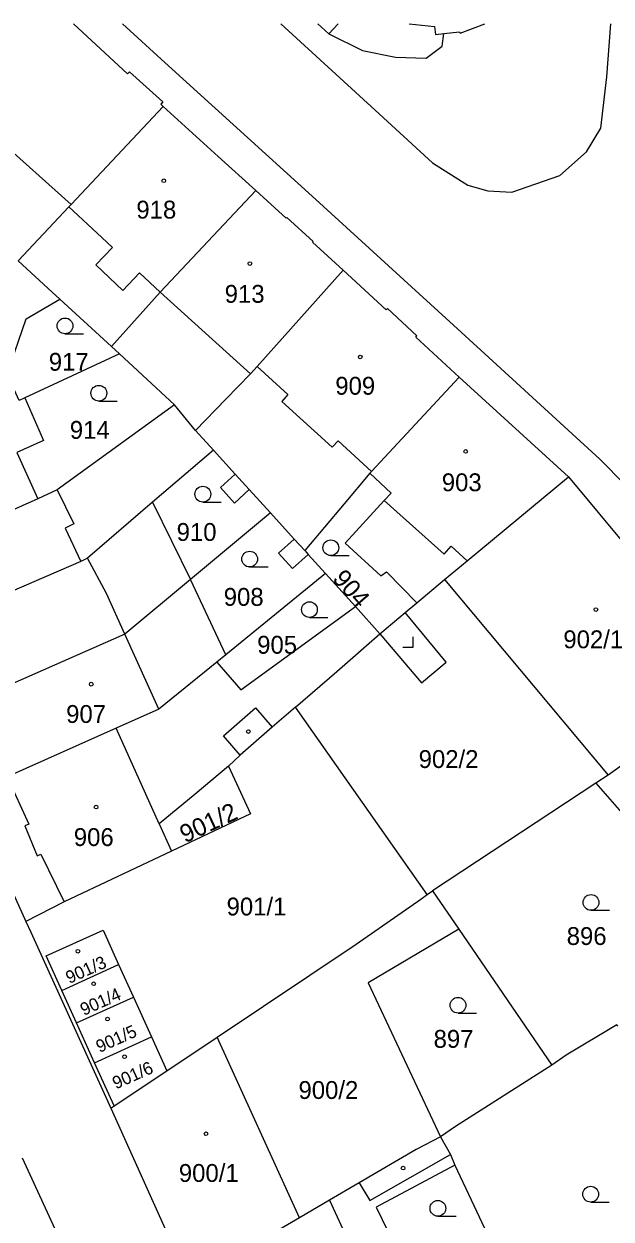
# Model space of a CAD drawing. Extents: x -496682 to -495907, y -1088575 to -1088018.
# Drawn here: x -496251.9 to -496196, y -1088133.3 to -1088019.5 of the extents above; entities that cross this region are included whole.
import ezdxf

# ---------------------------------------------------------------- set-up
doc = ezdxf.new("R2010")
doc.units = 0
for name, color, linetype in [('Hranice parcel', 7, 'Continuous'), ('Parcelní čísla', 7, 'Continuous'), ('Vnitřní kresba', 7, 'Continuous'), ('Značky budov', 7, 'Continuous'), ('Značky kultur', 7, 'Continuous')]:
    doc.layers.add(name, color=color, linetype=linetype)

msp = doc.modelspace()

# ---------------------------------------------------------------- linework, layer by layer
at = {"layer": 'Hranice parcel'}
for p, q in [((-496243.53, -1088050.21), (-496248.45, -1088045.69)), ((-496243.53, -1088050.21), (-496242.78, -1088050.9)), ((-496242.78, -1088050.9), (-496251.78, -1088055.1)), ((-496242.78, -1088050.9), (-496237.54, -1088055.74)), ((-496200.06, -1088062.62), (-496210.45, -1088053.11)), ((-496251.78, -1088055.1), (-496252.31, -1088055.35)), ((-496235.54, -1088058.2), (-496237.54, -1088055.74)), ((-496235.54, -1088058.2), (-496233.84, -1088060.08)), ((-496239.62, -1088065.03), (-496236.01, -1088072.37)), ((-496228.41, -1088066.04), (-496236.01, -1088072.37)), ((-496223.18, -1088071.81), (-496232.65, -1088079.55)), ((-496223.18, -1088071.81), (-496220.32, -1088074.97)), ((-496232.65, -1088079.55), (-496236.01, -1088072.37)), ((-496214.47, -1088074.6), (-496211.87, -1088072.4)), ((-496211.87, -1088072.4), (-496196.3, -1088091)), ((-496220.32, -1088074.97), (-496217.99, -1088077.55)), ((-496232.65, -1088079.55), (-496233.51, -1088080.25)), ((-496213.51, -1088102.38), (-496226.04, -1088084.55)), ((-496196.3, -1088091), (-496197.46, -1088091.77)), ((-496197.46, -1088091.77), (-496212.99, -1088102.02)), ((-496197.46, -1088091.77), (-496183.44, -1088107.88)), ((-496257.2, -1088092.78), (-496251.66, -1088104.94)), ((-496213.51, -1088102.38), (-496212.99, -1088102.02)), ((-496212.99, -1088102.02), (-496210.49, -1088105.69)), ((-496210.49, -1088105.69), (-496201.65, -1088118.63)), ((-496248.26, -1088111.5), (-496242.85, -1088109.04)), ((-496242.85, -1088109.04), (-496241.44, -1088112.14)), ((-496246.86, -1088114.6), (-496248.26, -1088111.5)), ((-496246.86, -1088114.6), (-496241.44, -1088112.14)), ((-496241.44, -1088112.14), (-496239.72, -1088115.94)), ((-496245.14, -1088118.39), (-496246.86, -1088114.6)), ((-496245.14, -1088118.39), (-496239.72, -1088115.94)), ((-496239.72, -1088115.94), (-496238.26, -1088119.15)), ((-496238.26, -1088119.15), (-496233.49, -1088115.96)), ((-496225.65, -1088133.15), (-496233.49, -1088115.96)), ((-496243.27, -1088122.51), (-496245.14, -1088118.39)), ((-496243.27, -1088122.51), (-496238.26, -1088119.15)), ((-496243.59, -1088122.72), (-496243.27, -1088122.51)), ((-496243.59, -1088122.72), (-496236.14, -1088139.28)), ((-496247.14, -1088138.02), (-496251.99, -1088127.48)), ((-496210.87, -1088128.14), (-496206.88, -1088136.59)), ((-496225.65, -1088133.15), (-496236.14, -1088139.28))]:
    msp.add_line(p, q, dxfattribs=at)
for points in [[(-496247.13, -1088019.49), (-496241.99, -1088024.25), (-496241.82, -1088024.06), (-496238.65, -1088026.91), (-496238.84, -1088027.12), (-496238.61, -1088027.35)], [(-496121.59, -1088147.94), (-496135.68, -1088131.58), (-496139.54, -1088127.1), (-496152.9, -1088111.52), (-496154.28, -1088109.93), (-496192.25, -1088065.81), (-496197.08, -1088060.92), (-496210.28, -1088048.82), (-496224.09, -1088036.2), (-496238.46, -1088023.17), (-496242.49, -1088019.49)], [(-496227.42, -1088019.49), (-496218.44, -1088027.69), (-496212.99, -1088032.72), (-496209.64, -1088034.85), (-496207.72, -1088035.39), (-496205.46, -1088035.51), (-496200.9, -1088033.92), (-496198.35, -1088031.67), (-496197, -1088029.41), (-496196.42, -1088024.53), (-496196.02, -1088019.49)], [(-496223.91, -1088019.49), (-496222.87, -1088020.43), (-496219.64, -1088022.03), (-496216.53, -1088022.64), (-496213.6, -1088022.74), (-496212.09, -1088021.59), (-496211.93, -1088020.4), (-496210.42, -1088020.24), (-496210.37, -1088020.38), (-496208.02, -1088019.49)], [(-496238.61, -1088027.35), (-496247.36, -1088036.67), (-496247.58, -1088036.9), (-496252.41, -1088042.06)], [(-496229.79, -1088035.36), (-496233.37, -1088032.11), (-496238.61, -1088027.35)], [(-496229.79, -1088035.36), (-496238.89, -1088045.04), (-496243.53, -1088050.21)], [(-496221.5, -1088042.93), (-496224.42, -1088040.26), (-496224.36, -1088040.2), (-496226.85, -1088037.91), (-496226.92, -1088037.98), (-496229.79, -1088035.36)], [(-496248.45, -1088045.69), (-496249.17, -1088045.03), (-496252.41, -1088042.06)], [(-496221.5, -1088042.93), (-496229.68, -1088052.09), (-496230.31, -1088052.79), (-496232.64, -1088055.2), (-496235.54, -1088058.2)], [(-496210.45, -1088053.11), (-496214.59, -1088049.3), (-496214.48, -1088049.18), (-496217.29, -1088046.57), (-496217.41, -1088046.7), (-496221.5, -1088042.93)], [(-496252.31, -1088055.35), (-496253.46, -1088052.82), (-496251.65, -1088047.57), (-496248.45, -1088045.69)], [(-496210.45, -1088053.11), (-496218.79, -1088062.09), (-496218.96, -1088062.26)], [(-496251.78, -1088055.1), (-496249.99, -1088059.14), (-496252.53, -1088060.29), (-496250.53, -1088064.7)], [(-496237.54, -1088055.74), (-496248.69, -1088063.85), (-496250.53, -1088064.7)], [(-496233.84, -1088060.08), (-496236.43, -1088062.3), (-496239.62, -1088065.03)], [(-496233.84, -1088060.08), (-496231.77, -1088062.35), (-496230.42, -1088063.83), (-496228.41, -1088066.04)], [(-496218.96, -1088062.26), (-496221.39, -1088065.17), (-496225.14, -1088069.61)], [(-496218.96, -1088062.26), (-496216.93, -1088064.15), (-496217.59, -1088064.87), (-496221.29, -1088068.92), (-496217.9, -1088072.02), (-496217.36, -1088071.64), (-496214.47, -1088074.6)], [(-496211.87, -1088072.4), (-496209.69, -1088070.6), (-496200.06, -1088062.62)], [(-496200.06, -1088062.62), (-496194.43, -1088069.4), (-496194.32, -1088069.3), (-496189.2, -1088075.46), (-496189.32, -1088075.56), (-496183.71, -1088082.3)], [(-496250.53, -1088064.7), (-496263.4, -1088070.45), (-496266.61, -1088071.89)], [(-496239.62, -1088065.03), (-496245.81, -1088070.34), (-496246.43, -1088070.68), (-496259.9, -1088076.48), (-496260.11, -1088076.62), (-496263.53, -1088078.19)], [(-496225.14, -1088069.61), (-496226.16, -1088068.53), (-496228.41, -1088066.04)], [(-496225.14, -1088069.61), (-496224.82, -1088070.01), (-496223.18, -1088071.81)], [(-496236.01, -1088072.37), (-496242.26, -1088077.59), (-496256.74, -1088083.98), (-496260.43, -1088085.68)], [(-496233.51, -1088080.25), (-496231.22, -1088082.89), (-496220.32, -1088074.97)], [(-496217.99, -1088077.55), (-496215.59, -1088075.54), (-496214.47, -1088074.6)], [(-496226.04, -1088084.55), (-496222.11, -1088081.13), (-496217.99, -1088077.55)], [(-496233.51, -1088080.25), (-496239.01, -1088084.74), (-496243.07, -1088086.55), (-496253.46, -1088091.18), (-496253.83, -1088091.34), (-496257.2, -1088092.78)], [(-496183.71, -1088082.3), (-496195.19, -1088090.23), (-496196.3, -1088091)], [(-496226.04, -1088084.55), (-496228.23, -1088086.45), (-496231.29, -1088089.11), (-496232.41, -1088090.16)], [(-496232.41, -1088090.16), (-496235.56, -1088092.82), (-496239, -1088095.64), (-496237.83, -1088098.24)], [(-496232.41, -1088090.16), (-496230.3, -1088094.69), (-496237.83, -1088098.24)], [(-496237.83, -1088098.24), (-496248.04, -1088103.06), (-496251.66, -1088104.94)], [(-496233.49, -1088115.96), (-496220.27, -1088107.11), (-496214.12, -1088102.81), (-496213.51, -1088102.38)], [(-496251.66, -1088104.94), (-496251.19, -1088105.96), (-496243.59, -1088122.72)], [(-496248.26, -1088111.5), (-496249.75, -1088108.22), (-496244.33, -1088105.76), (-496242.85, -1088109.04)], [(-496210.49, -1088105.69), (-496219.13, -1088110.78), (-496212.23, -1088125.45)], [(-496195.38, -1088114.92), (-496195.47, -1088114.8), (-496200.29, -1088117.66), (-496201.65, -1088118.63)], [(-496201.65, -1088118.63), (-496210.81, -1088124.46), (-496212.23, -1088125.45)], [(-496212.23, -1088125.45), (-496214.56, -1088126.66), (-496219.96, -1088129.82), (-496222.8, -1088131.48), (-496225.65, -1088133.15)], [(-496212.23, -1088125.45), (-496211.28, -1088127.13), (-496210.87, -1088128.14)], [(-496210.87, -1088128.14), (-496218.36, -1088132.15), (-496214.27, -1088140.54), (-496206.88, -1088136.59)]]:
    msp.add_lwpolyline(points, dxfattribs=at)
at = {"layer": 'Vnitřní kresba'}
for p, q in [((-496222.87, -1088020.43), (-496221.98, -1088019.49)), ((-496215.23, -1088019.49), (-496212.81, -1088019.74)), ((-496212.81, -1088019.74), (-496212.7, -1088020.48)), ((-496212.7, -1088020.48), (-496211.93, -1088020.4)), ((-496260.12, -1088025.28), (-496247.36, -1088036.67)), ((-496247.58, -1088036.9), (-496244.46, -1088039.81)), ((-496244.46, -1088039.81), (-496243.43, -1088040.77)), ((-496243.43, -1088040.77), (-496245.01, -1088042.43)), ((-496245.01, -1088042.43), (-496242.44, -1088044.87)), ((-496242.44, -1088044.87), (-496240.85, -1088043.19)), ((-496240.85, -1088043.19), (-496238.89, -1088045.04)), ((-496238.89, -1088045.04), (-496230.31, -1088052.79)), ((-496229.68, -1088052.09), (-496226.75, -1088054.78)), ((-496226.75, -1088054.78), (-496227.32, -1088055.43)), ((-496227.32, -1088055.43), (-496222.53, -1088059.8)), ((-496222.53, -1088059.8), (-496221.96, -1088059.18)), ((-496221.96, -1088059.18), (-496218.79, -1088062.09)), ((-496231.77, -1088062.35), (-496233.15, -1088063.61)), ((-496248.69, -1088063.85), (-496247.1, -1088067.1)), ((-496233.15, -1088063.61), (-496231.83, -1088065.11)), ((-496231.83, -1088065.11), (-496230.42, -1088063.83)), ((-496217.59, -1088064.87), (-496211.89, -1088069.96)), ((-496247.1, -1088067.1), (-496247.94, -1088067.51)), ((-496247.94, -1088067.51), (-496246.43, -1088070.68)), ((-496226.16, -1088068.53), (-496227.64, -1088069.87)), ((-496211.89, -1088069.96), (-496211.23, -1088069.22)), ((-496211.23, -1088069.22), (-496209.69, -1088070.6)), ((-496244.01, -1088073.72), (-496245.81, -1088070.34)), ((-496227.64, -1088069.87), (-496226.3, -1088071.35)), ((-496226.3, -1088071.35), (-496224.82, -1088070.01)), ((-496242.26, -1088077.59), (-496244.01, -1088073.72)), ((-496211.69, -1088080.24), (-496215.59, -1088075.54)), ((-496239.01, -1088084.74), (-496242.26, -1088077.59)), ((-496217.99, -1088077.55), (-496214.05, -1088082.21)), ((-496214.05, -1088082.21), (-496211.69, -1088080.24)), ((-496232.89, -1088087.27), (-496229.83, -1088084.61)), ((-496229.83, -1088084.61), (-496228.23, -1088086.45)), ((-496239, -1088095.64), (-496243.07, -1088086.55)), ((-496231.29, -1088089.11), (-496232.89, -1088087.27)), ((-496253.46, -1088091.18), (-496251.4, -1088095.68)), ((-496251.4, -1088095.68), (-496251.77, -1088095.85)), ((-496251.77, -1088095.85), (-496250.61, -1088098.7)), ((-496250.61, -1088098.7), (-496250.26, -1088098.52)), ((-496250.26, -1088098.52), (-496248.04, -1088103.06)), ((-496218.97, -1088131.5), (-496211.28, -1088127.13)), ((-496219.96, -1088129.82), (-496218.97, -1088131.5)), ((-496222.8, -1088131.48), (-496217.11, -1088143.84))]:
    msp.add_line(p, q, dxfattribs=at)
at = {"layer": 'Značky budov'}
for centre in [(-496238.55, -1088034.42), (-496230.36, -1088042.31), (-496219.87, -1088051.2), (-496209.84, -1088060.19), (-496197.46, -1088075.25), (-496245.45, -1088082.35), (-496230.51, -1088086.86), (-496244.99, -1088094.05), (-496246.72, -1088107.78), (-496245.22, -1088110.87), (-496243.9, -1088114.24), (-496242.28, -1088117.82), (-496234.54, -1088125.16), (-496215.79, -1088128.42)]:
    msp.add_circle(centre, 0.175, dxfattribs=at)
at = {"layer": 'Značky kultur'}
for p, q in [((-496247.95, -1088048.99), (-496246.2, -1088048.99)), ((-496244.73, -1088055.4), (-496242.98, -1088055.4)), ((-496234.84, -1088065.01), (-496233.09, -1088065.01)), ((-496222.67, -1088070.11), (-496220.92, -1088070.11)), ((-496230.39, -1088071.19), (-496228.64, -1088071.19)), ((-496224.7, -1088076), (-496222.95, -1088076)), ((-496215.82, -1088078.84), (-496214.82, -1088078.84)), ((-496214.82, -1088078.84), (-496214.82, -1088077.84)), ((-496197.92, -1088103.88), (-496196.17, -1088103.88)), ((-496210.57, -1088113.67), (-496208.82, -1088113.67)), ((-496197.95, -1088131.66), (-496196.2, -1088131.66)), ((-496212.48, -1088133.01), (-496210.73, -1088133.01))]:
    msp.add_line(p, q, dxfattribs=at)
for centre in [(-496247.95, -1088048.24), (-496244.73, -1088054.65), (-496234.84, -1088064.26), (-496222.67, -1088069.36), (-496230.39, -1088070.44), (-496224.7, -1088075.25), (-496197.92, -1088103.13), (-496210.57, -1088112.92), (-496197.95, -1088130.91), (-496212.48, -1088132.26)]:
    msp.add_circle(centre, 0.75, dxfattribs=at)

# ---------------------------------------------------------------- texts
at = {"layer": 'Parcelní čísla'}
for s, p in [('918', (-496241.16, -1088038.02)), ('913', (-496232.76, -1088046.04)), ('917', (-496249.49, -1088052.51)), ('909', (-496222.24, -1088054.79)), ('914', (-496247.49, -1088058.99)), ('903', (-496212.11, -1088063.98)), ('910', (-496237.33, -1088068.71)), ('908', (-496232.85, -1088074.89)), ('905', (-496229.67, -1088079.45)), ('902/1', (-496200.55, -1088078.93)), ('907', (-496247.84, -1088086.04)), ('902/2', (-496214.31, -1088090.33)), ('906', (-496247.11, -1088097.76)), ('901/1', (-496232.58, -1088104.37)), ('896', (-496200.23, -1088107.18)), ('897', (-496212.89, -1088116.97)), ('900/2', (-496225.74, -1088121.84)), ('900/1', (-496237.12, -1088129.74))]:
    msp.add_text(s, height=1.7, dxfattribs=at).set_placement(p)
for s, height, rotation, p in [('904', 1.7, 311, (-496222.59, -1088072.36)), ('901/2', 1.7, 25, (-496236.53, -1088097.51)), ('901/3', 1.2, 24, (-496247.55, -1088110.9)), ('901/4', 1.2, 24, (-496246.17, -1088113.94)), ('901/5', 1.2, 24, (-496244.67, -1088117.47)), ('901/6', 1.2, 24, (-496243.11, -1088120.94))]:
    msp.add_text(s, height=height, rotation=rotation, dxfattribs=at).set_placement(p)

doc.saveas('drawing.dxf')
